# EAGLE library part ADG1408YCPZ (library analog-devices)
4 Ohm RON, 8-Channel, ±15 V/+12 V/±5 V iCMOS Multiplexers Source: 8x ADG1408_1409.pdf
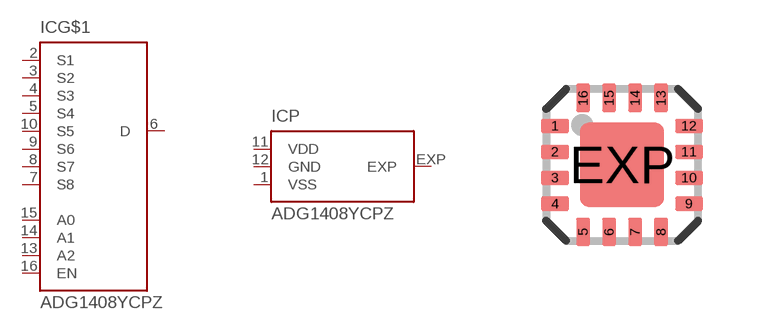
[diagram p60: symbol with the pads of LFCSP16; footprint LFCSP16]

Designator prefix IC; gates G$1=ADG1408 P=PWR-VSS_GND_VDD_EXP

## ADG1408YCPZ (MPN: ADG1408YCPZ-REEL7; OC_FARNELL: 1438940; OC_NEWARK: 28M3585)  [LFCSP16]
1  P:VSS  pwr
2  G$1:S1
3  G$1:S2
4  G$1:S3
5  G$1:S4
6  G$1:D
7  G$1:S8
8  G$1:S7
9  G$1:S6
10  G$1:S5
11  P:VDD  pwr
12  P:GND  pwr
13  G$1:A2  in
14  G$1:A1  in
15  G$1:A0  in
16  G$1:EN  in
EXP  P:EXP  pas

## Footprint LFCSP16 (pad centres in mm)
16-Terminal Leadless Frame Chip Scale Package [LFCSP] (CP) Source: Analog Devices .. 780914713ADD8704_0.pdf
smd 0.7 x 0.35: 1 -1.675,0.975; 2 -1.675,0.325; 3 -1.675,-0.325; 4 -1.675,-0.975; 9 1.675,-0.975; 10 1.675,-0.325; 11 1.675,0.325; 12 1.675,0.975
smd 0.35 x 0.7: 5 -0.975,-1.675; 6 -0.325,-1.675; 7 0.325,-1.675; 8 0.975,-1.675; 13 0.975,1.675; 14 0.325,1.675; 15 -0.325,1.675; 16 -0.975,1.675
smd 2.1 x 2.1: EXP 0,0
